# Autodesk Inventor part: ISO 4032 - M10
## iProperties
Comments: To add or edit properties for Autodesk Inventor files, use iProperties.
Created: 2004-08
Part Number: ISO 4032 - M10
Vendor: Autodesk Inc.
Document SubType Name: Modeling
Designer: John Blackburn
Material: Default
Description: Hex Nut
Standard: ISO 4032
Alert: To add or edit properties for Autodesk Inventor files, use iProperties.
Control State: 0
Master: False
Checked Out: False
Shininess: 64.0
Length Units: 11269
Angle Units: 11279
Time Units: 11290
Mass Units: 11283
Length Display Precision: 3
Angle Display Precision: 2
Compacted: True
EGR: 1
Density: 0.0
Volumn: 0.0
Area: 0.0
PropertySet Name: Model Information
Author: John Blackburn
Revision Number: 8
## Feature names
1. Body [Extrusion]
2. Chamfer1 [Revolution]
3. Thread [Hole]
4. Chamfer2
5. Chamfer3
